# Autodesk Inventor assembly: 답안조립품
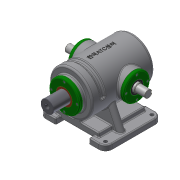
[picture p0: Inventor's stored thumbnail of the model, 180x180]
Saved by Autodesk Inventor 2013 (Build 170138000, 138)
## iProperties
Created: 2018-06
Part Number: 답안조립품
Document SubType Name: Assembly
Designer: Administrator
Mass: 8560.46 g
Surface Area: 4294.68 cm^2
Volume: 2307.06 cm^3
Density: 3.71055 g/cm^3
Author: Administrator
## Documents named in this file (13)
- C:\Users\Administrator\Desktop\380628V1007\답안조립품.iam
- C:\Users\Administrator\Desktop\380628V1007\본체.ipt
- C:\Users\Administrator\Desktop\380628V1007\가변스프링.ipt
- C:\Users\Administrator\Desktop\380628V1007\베어링 6205.ipt
- 베어링 6205.ipt
- C:\Users\Administrator\Desktop\380628V1007\볼트 M4.ipt
- C:\Users\Administrator\Desktop\380628V1007\부시.ipt
- C:\Users\Administrator\Desktop\380628V1007\슬라이드 커버.ipt
- C:\Users\Administrator\Desktop\380628V1007\슬라이드.ipt
- C:\Users\Administrator\Desktop\380628V1007\오일실.ipt
- 오일실.ipt
- C:\Users\Administrator\Desktop\380628V1007\축 커버.ipt
- C:\Users\Administrator\Desktop\380628V1007\편심축.ipt
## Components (1 placed, 1 different names)
1. 가변스프링:1
